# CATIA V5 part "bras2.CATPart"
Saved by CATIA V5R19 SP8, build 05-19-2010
Part number: bras1.1
Publications: "longueur_bras1", "longueur_lumière"
Bounding box of the stored display mesh (mm): x 0 to 10, y -620 to 20, z 0 to 40
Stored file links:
  G:\EU_thinkMotion\CFAO_2010\SIL_groupe1\SIL_groupe1\A reprendre\fbruguiere\fbruguiere\fbruguiere\bras2.CATPart
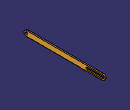
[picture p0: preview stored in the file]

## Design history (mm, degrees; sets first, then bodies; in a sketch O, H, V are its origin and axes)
Parameters
  longueur_bras1 = 600
  `longueur_lumière` = 120
Body1 (main body)
  Sketch1 on yz-plane, origin (0, 0, 0), H (0, 1, 0), V (0, 0, 1)
    line L1 (0, 0) -> (-600, 0)
    line L2 (-600, 40) -> (0, 40)
    arc A1 centre (-600, 20) radius 20 from (-600, 40) to (-600, 0) ccw
    arc A2 centre (0, 20) radius 20 from (0, 0) to (0, 40) ccw
    length L1 = 600 {= longueur_bras1 *1mm}
    distance L2 L1 = 40
    radius A1 = 20
    horizontal: L1 H, L2 H
    tangency: A1 L1, A2 L1
  Pad1: profile Sketch1, direction (1, 0, 0), length 10
  Sketch2 on end face of Pad1, origin (10, 0, 0), H (0, 1, 0), V (0, 0, 1)
    circle A1 centre (-600, 20) radius 10
    arc A2 centre (0, 20) radius 10 from (-0.387, 10.0075) to (-0.3981, 29.9921) ccw
    point P2 (0, 20)
    arc A3 centre (-120, 20.0015) radius 10 from (-120, 30.0015) to (-119.9995, 10.0015) ccw
    point P3 (-120, 20.0015)
    line L1 (-120, 30.0015) -> (-0.3981, 29.9921)
    line L2 (-0.387, 10.0075) -> (-119.9995, 10.0015)
    radius A2 = 10
    radius A3 = 10
    distance P3 P2 = 120 {= `longueur_lumière` *1mm}
    coincidence: P2 V
    tangency: L2 A3
  Pocket1: profile Sketch2, direction (-1, 0, 0), through (limit type 6)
